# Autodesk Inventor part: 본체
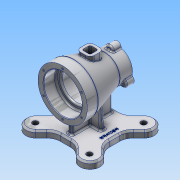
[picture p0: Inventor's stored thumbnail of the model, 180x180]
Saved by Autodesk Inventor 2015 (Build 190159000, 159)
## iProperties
Created: 2018-03
Part Number: 본체
Material: 알루미늄 6061
Document SubType Name: Modeling
Designer: SCD-A03
Density: 2.7 g/cm^3
Appearance: 알루미늄 - 평지
Mass: 1014.9 g
Surface Area: 858.039 cm^2
Volume: 375.89 cm^3
Author: SCD-A03
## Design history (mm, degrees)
sketch "스케치2"
  geometry: C1 r 45 at (0, 0); 1 further point
  constraints: 1 centre point, 1 coincident
  dimensions: "d3" = 90 diameter of C1
extrude "돌출2" new body sketch "스케치2" distance "d4" = 20; taper "d5" = 0 deg
node "작업 평면3"
sketch "스케치3"
  geometry: C1 r 27.5 at (0, 0); 1 further point
  constraints: 1 centre point, 1 coincident
  dimensions: "d9" = 55 diameter of C1
extrude "돌출3" join sketch "스케치3" distance "d10" = 23; taper "d11" = 0 deg
sketch "스케치4"
  geometry: L1 (0, -45)-(-20, -45) reference; L2 (-20, -45)-(-20, 45) reference; L3 (-20, 45)-(0, 45) reference; L4 (0, 45)-(0, -45) reference; L5 (57, 27.5)-(80, 27.5) reference; L6 (80, 27.5)-(80, -27.5) reference; L7 (80, -27.5)-(57, -27.5) reference; L8 (57, -27.5)-(57, 27.5) reference; L9 (0, 45)-(57, 27.5); L10 (57, 27.5)-(57, 0); L11 (57, 0)-(0, 0); L12 (0, 45)-(0, 0)
  constraints: 8 end point, 1 collinear, 1 midpoint, 1 perpendicular
revolve "회전1" sketch "스케치4" stored, may be unused: angle "d12" = 90 deg
node "작업 평면4"
sketch "스케치5"
  geometry: L1 (-12.5, 17.5)-(12.5, 17.5); L2 (12.5, 17.5)-(12.5, 42.5); L3 (12.5, 42.5)-(-12.5, 42.5); L4 (-12.5, 42.5)-(-12.5, 17.5); L5 (-12.5, 17.5)-(12.5, 42.5); L6 (12.5, 17.5)-(-12.5, 42.5); L7 (-45, -20)-(45, -20) reference; 2 further points
  constraints: 12 end point, 2 midpoint, 2 parallel, 1 horizontal, 1 perpendicular
  dimensions: "d14" = 25 distance of L3.end L2.end; "d15" = 25 distance of L2.end L1.end; "d218" = 50 distance from line of point (0, 30) L7
extrude "돌출4" join sketch "스케치5" stored distance "d16" = 23; taper "d17" = 0 deg
sketch "스케치6"
  geometry: L1 (57, -27.5)-(0, -45) reference; L2 (0, -45)-(-20, -45) reference; L3 (-20, -45)-(-20, 45) reference; L4 (-20, 45)-(0, 45) reference; L5 (0, 45)-(17.5, 39.627) reference; L6 (17.5, 39.627)-(17.5, 45) reference; L7 (17.5, 45)-(42.5, 45) reference; L8 (42.5, 45)-(42.5, 31.952) reference; L9 (42.5, 31.952)-(57, 27.5) reference; L10 (57, 27.5)-(80, 27.5) reference; L11 (80, 27.5)-(80, -27.5) reference; L12 (80, -27.5)-(57, -27.5) reference; L13 (-20, 0)-(80, 0); L14 (-20, 35)-(3, 35); L15 (3, 35)-(3, 26); L16 (3, 26)-(50, 26); L17 (50, 26)-(50, 20); L18 (50, 20)-(80, 20); 1 further point
  constraints: 12 end point, 4 perpendicular, 2 midpoint, 2 point on line, 1 horizontal
  dimensions: "d18" = 23 distance of L14.start L14.end; "d19" = 47 distance of L15.end L16.end; "d20" = 35 distance between parallel lines of L13 L14; "d21" = 26 distance between parallel lines of L13 L16; "d22" = 20 distance between parallel lines of L13 L18
revolve "회전2" sketch "스케치6" stored, may be unused: angle "d23" = 90 deg
sketch "스케치7"
  geometry: L1 (-7.5, 22.5)-(7.5, 22.5); L2 (7.5, 22.5)-(7.5, 37.5); L3 (7.5, 37.5)-(-7.5, 37.5); L4 (-7.5, 37.5)-(-7.5, 22.5); L5 (-7.5, 22.5)-(7.5, 37.5); L6 (7.5, 22.5)-(-7.5, 37.5); L7 (-45, -20)-(45, -20) reference; 2 further points
  constraints: 12 end point, 2 midpoint, 2 parallel, 1 horizontal, 1 perpendicular
  dimensions: "d24" = 15 distance of L3.end L2.end; "d25" = 15 distance of L2.end L1.end; "d219" = 50 distance from line of L7 point (0, 30)
extrude "돌출5" cut sketch "스케치7" stored distance "d26" = 23; taper "d27" = 0 deg
node "작업 평면5"
sketch "스케치10"
  geometry: C1 r 35 at (0, 0) reference; 1 further point
  dimensions: "d59" = 40 distance of point (0, 40) C1.centre
hole "구멍2" sketch "스케치10" at (0, 40) diameter "d60" = 3.242; stored, may be unused: countersink angle "d64" = 90 deg, drill point angle "d66" = 118 deg; dims "d61" = 9, "d62" = 4, "d63" = 2, "d65" = 11
sketch "스케치11"
  geometry: C1 r 7 at (0, -27.5); 1 further point
  constraints: 1 centre point, 1 vertical alignment, 1 other
  dimensions: "d70" = 14 diameter of C1
extrude "돌출8" join sketch "스케치11" distance "d71" = 15; taper "d72" = 0 deg
hole "구멍3" diameter "d78" = 3.242; stored, may be unused: countersink angle "d82" = 90 deg, drill point angle "d84" = 118 deg; dims "d76" = 10, "d77" = 10, "d79" = 9, "d80" = 4, "d81" = 2, "d83" = 11
fillet "모깎기1" dims "d88" = 8
fillet "모깎기2" dims "d89" = 3
fillet "모깎기3" dims "d90" = 3
fillet "모깎기4" dims "d91" = 3
node "작업 평면7"
fillet "모깎기8" dims "d135" = 3
fillet "모깎기9" dims "d136" = 3
fillet "모깎기10" dims "d137" = 3
chamfer "모따기5" distance "d143" = 1; stored, may be unused: second distance "d144" = 2, angle "d145" = 45 deg
node "작업 평면10"
sketch "스케치19"
  geometry: L1 (-26, 47)-(26, 47) reference; L2 (7.5, 25.5)-(7.5, 34.5) reference; L3 (4.5, 37.5)-(-4.5, 37.5) reference; L4 (-7.5, 34.5)-(-7.5, 25.5) reference; L5 (-4.5, 22.5)-(4.5, 22.5) reference; L6 (26, 6)-(-26, 6) reference; L7 (-7.5, 30)-(0, 30); L8 (0, 30)-(0, 37.5); L9 (-45, -15)-(45, -15); L10 (45, -15)-(45, 75); L11 (45, 75)-(-45, 75); L12 (-45, 75)-(-45, -15); L13 (-45, -15)-(45, 75); L14 (45, -15)-(-45, 75); L15 (0, 30)-(49.497, 79.497); L16 (45, -15)-(-45, 75); L17 (45, 75)-(-45, -15); L18 (-45, 75)-(45, -15); L19 (49.497, 79.497)-(31.497, 97.497); L20 (-49.497, 79.497)-(-36.77, 92.225); L21 (-36.77, 92.225)-(62.225, -6.77); L22 (-62.225, 66.77)-(36.77, -32.225); L23 (-36.77, -32.225)-(62.225, 66.77); L24 (-62.225, -6.77)-(36.77, 92.225); L25 (4.5, 22.5)-(-4.5, 22.5) reference; L26 (-7.5, 25.5)-(-7.5, 34.5) reference; L27 (-4.5, 37.5)-(4.5, 37.5) reference; L28 (7.5, 34.5)-(7.5, 25.5) reference; A1 r 18 centre (49.497, 79.497) between (62.225, 66.77) and (36.77, 92.225); A2 r 18 centre (-49.497, 79.497) between (-36.77, 92.225) and (-62.225, 66.77); A3 r 18 centre (-49.497, -19.497) between (-36.77, -32.225) and (-62.225, -6.77); A4 r 18 centre (49.497, -19.497) between (62.225, -6.77) and (36.77, -32.225); 1 further point
  constraints: 36 end point, 8 point on circle, 4 centre point, 4 midpoint, 2 horizontal, 2 parallel, 2 perpendicular, 2 tangent, 1 coincident, 1 point on line, 25 other
  dimensions: "d178" = 90 distance of L11.end L10.end; "d179" = 90 distance of L10.end L9.end; "d180" = 70 distance of L7.end L15.end; "d181" = 36 diameter of A1; "d184" = 360 deg dimension on L7.end L19.start (derived)
extrude "돌출14" join sketch "스케치19" distance "d186" = 12; taper "d187" = 0 deg
sketch "스케치20"
  geometry: L1 (-4, -7)-(4, -7); L2 (4, -7)-(4, 67); L3 (4, 67)-(-4, 67); L4 (-4, 67)-(-4, -7); L5 (-4, -7)-(4, 67); L6 (4, -7)-(-4, 67); L7 (-19.544, -15)-(19.544, -15) reference; 2 further points
  constraints: 12 end point, 2 midpoint, 2 parallel, 1 horizontal, 1 perpendicular
  dimensions: "d188" = 8 distance of L3.end L2.end; "d189" = 74 distance of L2.end L1.end; "d220" = 8 distance between parallel lines of L1 L7
extrude "돌출15" join sketch "스케치20" stored distance "d190" = 12; taper "d191" = 0 deg
node "작업 평면11"
sketch "스케치21"
  geometry: L1 (-3.5, -94.895)-(-3.5, -115) reference; L2 (-3.5, -115)-(-8.5, -115) reference; L3 (-8.5, -115)-(-8.5, -103.536) reference; L4 (0, -34.435)-(0, 0) reference; L5 (0, 0)-(-41, 0) reference; L6 (-41, 0)-(-41, 12) reference; L7 (-41, 12)-(49, 12) reference; L8 (49, 12)-(49, 0) reference; L9 (49, 0)-(8, 0) reference; L10 (8, 0)-(8, -34.435) reference; L11 (16.5, -103.536)-(16.5, -115) reference; L12 (16.5, -115)-(11.5, -115) reference; L13 (11.5, -115)-(11.5, -94.895) reference; L14 (4, 6)-(4, -41.14); L15 (4, 6)-(28, 6); L16 (4, 6)-(28, 6); L17 (28, 6)-(28, 0); L18 (28, 6)-(42.578, 6); L19 (28, 0)-(24.322, -42.041); L20 (28, 0)-(70.201, 0); L21 (24.322, -42.041)-(4, -41.14); L22 (4, 6)-(-20, 6); L23 (-20, 0)-(-16.322, -42.041); L24 (-20, 6)-(-20, 0); L25 (-16.322, -42.041)-(4, -41.14); L26 (4, 6)-(-20, 4.199); L27 (4, 6)-(28, 3); A1 r 26 centre (4, -70) between (11.5, -94.895) and (-3.5, -94.895) reference; A2 r 35.789 centre (4, -70) between (0, -34.435) and (-8.5, -103.536) reference; A3 r 35.789 centre (4, -70) between (16.5, -103.536) and (8, -34.435) reference; 3 further points
  constraints: 28 end point, 4 horizontal, 4 symmetric about line, 2 equal length, 2 point on line, 1 midpoint, 1 vertical
  dimensions: "d192" = 24 distance of L14.start L15.end; "d193" = 0 distance between parallel lines of L15 L16 (derived); "d194" = 90 deg angle of L17 L18; "d195" = 95 deg angle of L19 L20
extrude "돌출16" join sketch "스케치21" stored distance "d196" = 8; taper "d197" = 0 deg
fillet "모깎기15" dims "d198" = 3
fillet "모깎기16" dims "d199" = 3
sketch "스케치22"
  geometry: A1 r 15 centre (-49.497, -20.545) between (-60.104, -9.939) and (-38.891, -31.152) reference; A2 r 15 centre (49.497, -20.545) between (38.891, -31.152) and (60.104, -9.939) reference; A3 r 15 centre (49.497, 78.45) between (60.104, 67.843) and (38.891, 89.056) reference; A4 r 15 centre (-49.497, 78.45) between (-38.891, 89.056) and (-60.104, 67.843) reference; 1 further point
hole "구멍5" sketch "스케치22" at (49.497, 78.45), (-49.497, 78.45), (49.497, -20.545), (-49.497, -20.545) diameter "d203" = 10; stored, may be unused: countersink angle "d207" = 90 deg, drill point angle "d209" = 118 deg; dims "d204" = 6, "d205" = 4, "d206" = 2, "d208" = 8
sketch "스케치23"
  geometry: L1 (19.544, 75)-(-19.544, 75) reference; 2 further points
  constraints: 1 other
  dimensions: "d216" = 45 distance from line of L1 point (35, 30); "d217" = 35 horizontal distance of point (0, 0) point (35, 30)
feature "엠보싱2" sketch "스케치23" dims "d3" = 90, "d13" = 45, "d210" = 0.5, "d211" = 0
fillet "모깎기17" dims "d212" = 25
chamfer "모따기7" distance "d213" = 3; stored, may be unused: second distance "d214" = 2, angle "d215" = 45 deg
fillet "모깎기18" dims "d221" = 1
node "솔리드2"
pattern_circular "원형 패턴1" dims angle "d68" = 360 deg
pattern_circular "원형 패턴2" dims angle "d74" = 360 deg
pattern_circular "원형 패턴3" dims angle "d86" = 360 deg
node "투영된 루프3"
node "절단 모서리 투영1"
node "절단 모서리 투영2"
node "절단 모서리 투영6"
other parameters: "d28" = -82, "d92" = -82, "d177" = -82
